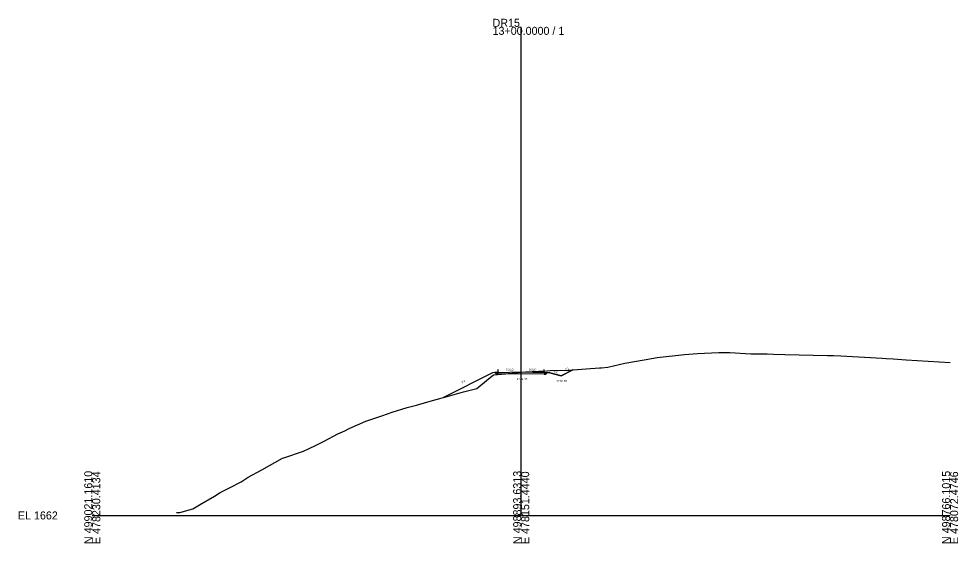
# Model space of a CAD drawing. Extents: x -26 to 303, y -10 to 4126.
# Drawn here: x -25.7 to 302.8, y 2990.3 to 3173.6 of the extents above; entities that cross this region are included whole.
import ezdxf

# ---------------------------------------------------------------- set-up
doc = ezdxf.new("R2010")
doc.units = 0
for name, color, linetype in [('Exist Cross Section Cell', 7, 'Continuous'), ('Exist XS Center Line Elevation Label', 7, 'Continuous'), ('Exist XS Ground Line', 7, 'Continuous'), ('Prop XS Ditch Slope Text', 7, 'Continuous'), ('Prop XS Ditch Standard Text', 7, 'Continuous'), ('Prop XS Earthwork Shape', 7, 'Continuous'), ('Prop XS EOT Tick Mark', 7, 'Continuous'), ('Prop XS Finish Grade', 7, 'Continuous'), ('Prop XS Finish Grade Earthwork', 7, 'Continuous'), ('Prop XS Finish Grade Pavement', 7, 'Continuous'), ('Prop XS Pvmt Edge Slope', 7, 'Continuous'), ('Prop XS SE Text', 7, 'Continuous'), ('Prop XS Side Slope Text', 7, 'Continuous'), ('Prop XS Subgrade Earthwork', 7, 'Continuous')]:
    doc.layers.add(name, color=color, linetype=linetype)

msp = doc.modelspace()

# ---------------------------------------------------------------- linework, layer by layer
at = {"layer": 'Exist Cross Section Cell'}
for p, q in [((150, 3000), (150, 3170.77)), ((0, 3000), (150, 3000)), ((150, 3000), (300, 3000))]:
    msp.add_line(p, q, dxfattribs=at)
at = {"layer": 'Exist XS Ground Line'}
msp.add_lwpolyline([(29.47, 3000.98), (30.67, 3001.04), (35.13, 3002.29), (37.5, 3003.67), (42.79, 3006.76), (44.76, 3007.97), (47.94, 3009.62), (52.03, 3011.74), (54.56, 3013.34), (59.29, 3015.9), (66.56, 3019.98), (66.94, 3020.13), (73.82, 3022.42), (78.09, 3024.41), (81.09, 3025.95), (85.94, 3028.53), (88.35, 3029.54), (89.85, 3030.35), (95.62, 3033), (101.62, 3034.98), (102.89, 3035.44), (104.94, 3036.06), (110.15, 3037.68), (113.38, 3038.51), (118.97, 3040.17), (124.9, 3041.86), (129.82, 3043.21), (134.55, 3044.36), (137.89, 3047.2), (140.33, 3049.13), (144.5, 3049.48), (150, 3050.08), (151.5, 3050.25), (156.03, 3050.38), (157.69, 3050.47), (160.17, 3050.61), (166.63, 3050.76), (172.77, 3051.24), (177.41, 3051.57), (178.06, 3051.58), (180.29, 3051.83), (184.32, 3052.74), (186.26, 3053.26), (192.98, 3054.39), (197.52, 3055.22), (207.06, 3056.2), (211.69, 3056.62), (219.12, 3056.92), (222.93, 3056.92), (230.27, 3056.54), (234.06, 3056.44), (236.05, 3056.5), (238.24, 3056.39), (242.18, 3056.3), (257.1, 3055.95), (259.26, 3055.85), (261.78, 3055.8), (276.29, 3054.99), (277.67, 3054.87), (280.13, 3054.69), (284.6, 3054.39), (300, 3053.41)], dxfattribs=at)
at = {"layer": 'Prop XS Earthwork Shape'}
for points in [[(122.84, 3041.27), (124.9, 3041.86), (129.82, 3043.21), (134.55, 3044.36), (137.89, 3047.2), (140.33, 3049.13), (143.15, 3049.37), (142, 3049.34), (141.32, 3049.33), (140.74, 3049.91), (140, 3049.85)], [(158, 3049.34), (150, 3049.5), (143.15, 3049.37), (144.5, 3049.48), (150, 3050.08), (151.5, 3050.25), (156.03, 3050.38), (157.69, 3050.47), (160.17, 3050.61), (166.63, 3050.76), (168.05, 3050.87), (164, 3048.85), (160, 3049.85), (159.26, 3049.91), (158.68, 3049.33)]]:
    msp.add_lwpolyline(points, close=True, dxfattribs=at)
at = {"layer": 'Prop XS EOT Tick Mark'}
for p, q in [((142, 3050.01), (142, 3051.01)), ((158, 3050.01), (158, 3051.01))]:
    msp.add_line(p, q, dxfattribs=at)
at = {"layer": 'Prop XS Finish Grade'}
for p, q in [((142, 3050.01), (140.74, 3049.91)), ((158, 3050.01), (159.26, 3049.91))]:
    msp.add_line(p, q, dxfattribs=at)
at = {"layer": 'Prop XS Finish Grade Earthwork'}
for p, q in [((140, 3049.85), (122.84, 3041.27)), ((140.74, 3049.91), (140, 3049.85)), ((159.26, 3049.91), (160, 3049.85)), ((160, 3049.85), (164, 3048.85)), ((164, 3048.85), (168.05, 3050.87))]:
    msp.add_line(p, q, dxfattribs=at)
at = {"layer": 'Prop XS Finish Grade Pavement'}
for p, q in [((142, 3050.01), (150, 3050.17)), ((150, 3050.17), (158, 3050.01))]:
    msp.add_line(p, q, dxfattribs=at)
at = {"layer": 'Prop XS Pvmt Edge Slope'}
for p, q in [((142, 3050.01), (141.32, 3049.33)), ((158, 3050.01), (158.68, 3049.33))]:
    msp.add_line(p, q, dxfattribs=at)
at = {"layer": 'Prop XS Subgrade Earthwork'}
for p, q in [((141.32, 3049.33), (140.74, 3049.91)), ((142, 3049.34), (141.32, 3049.33)), ((150, 3049.5), (142, 3049.34)), ((158, 3049.34), (150, 3049.5)), ((158, 3049.34), (158.68, 3049.33)), ((158.68, 3049.33), (159.26, 3049.91))]:
    msp.add_line(p, q, dxfattribs=at)

# ---------------------------------------------------------------- texts
at = {"layer": 'Exist Cross Section Cell'}
for s, p in [('13+00.0000 / 1', (140, 3167.97)), ('DR15', (140, 3170.77)), ('EL 1662', (-26, 2998.6))]:
    msp.add_text(s, height=2.8, dxfattribs=at).set_placement(p)
for s, p in [('N 499021.1610', (0, 2990)), ('E 478230.4134', (2.8, 2990)), ('N 498893.6313', (150, 2990)), ('E 478151.4440', (152.8, 2990)), ('N 498766.1015', (300, 2990)), ('E 478072.4746', (302.8, 2990))]:
    msp.add_text(s, height=2.8, rotation=90, dxfattribs=at).set_placement(p)
at = {"layer": 'Exist XS Center Line Elevation Label'}
msp.add_text('1712.08', height=0.75, dxfattribs=at).set_placement((148.41, 3047.33))
at = {"layer": 'Prop XS Ditch Slope Text'}
msp.add_text('4:1', height=0.75, rotation=345.9638, dxfattribs=at).set_placement((161.27, 3050.01))
at = {"layer": 'Prop XS Ditch Standard Text'}
msp.add_text('1710.85', height=0.75, dxfattribs=at).set_placement((162.29, 3046.6))
at = {"layer": 'Prop XS SE Text'}
for rotation, p in [(1.1458, (144.69, 3050.56)), (358.8542, (152.69, 3050.62))]:
    msp.add_text('0.020', height=0.75, rotation=rotation, dxfattribs=at).set_placement(p)
at = {"layer": 'Prop XS Side Slope Text'}
for p in [(165.53, 3050.48), (129.27, 3046.16)]:
    msp.add_text('2:1', height=0.75, rotation=26.5651, dxfattribs=at).set_placement(p)

doc.saveas('drawing.dxf')
